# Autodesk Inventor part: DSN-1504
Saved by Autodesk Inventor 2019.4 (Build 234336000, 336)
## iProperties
Created: 2020-03
Part Number: DSN-1504
Material: Generic
Document SubType Name: Modeling
Designer: Administrator
Density: 1 g/cm^3
Appearance: Default
Title: DSN-1504
Author: Administrator
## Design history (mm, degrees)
feature "DSN-1504"
body "Solid1"
